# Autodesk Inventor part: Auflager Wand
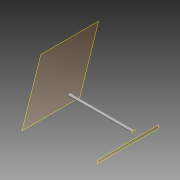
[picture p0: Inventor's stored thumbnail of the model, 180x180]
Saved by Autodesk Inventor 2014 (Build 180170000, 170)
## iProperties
Created: 2013-09
Part Number: Auflager Wand
Material: Stahl
Document SubType Name: Modeling
Designer: Stefan Tammegger
Mass: 71875.7 g
Surface Area: 45818.1 cm^2
Volume: 9156.13 cm^3
Density: 7.85 g/cm^3
Appearance: Stahl
Author: Stefan Tammegger
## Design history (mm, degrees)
node "Blöcke"
  sketch "FR 160_80_4"
    geometry: L1 (-2916.646, 2613.194)-(-2844.646, 2613.194); L2 (-2840.646, 2609.194)-(-2840.646, 2457.194); L3 (-2844.646, 2453.194)-(-2916.646, 2453.194); L4 (-2920.646, 2457.194)-(-2920.646, 2609.194); L5 (-2844.646, 2609.194)-(-2916.646, 2609.194); L6 (-2916.646, 2609.194)-(-2916.646, 2457.194); L7 (-2916.646, 2457.194)-(-2844.646, 2457.194); L8 (-2844.646, 2457.194)-(-2844.646, 2609.194); A1 r 4 centre (-2916.646, 2609.194) between (-2916.646, 2613.194) and (-2920.646, 2609.194); A2 r 4 centre (-2844.646, 2609.194) between (-2840.646, 2609.194) and (-2844.646, 2613.194); A3 r 4 centre (-2916.646, 2457.194) between (-2920.646, 2457.194) and (-2916.646, 2453.194); A4 r 4 centre (-2844.646, 2457.194) between (-2844.646, 2453.194) and (-2840.646, 2457.194); 4 further points
    constraints: 16 end point, 8 point on circle, 8 tangent, 6 point on line, 4 centre point, 4 parallel, 3 equal radius, 2 perpendicular, 1 horizontal, 1 midpoint, 3 other
    dimensions: "d0" = 80 distance of point (-2840.646, 2453.194) point (-2920.646, 2453.194); "d1" = 160 distance of point (-2840.646, 2613.194) point (-2840.646, 2453.194); "d2" = 4 distance between parallel lines of L1 L5; "d3" = 4 radius of A1
workplane "Arbeitsebene1"
sketch "Skizze1"
  geometry: L1 (-2996, 2490)-(-2924, 2490) reference; L2 (0, 30)-(-3300, 30) reference; L3 (0, 3800)-(0, -80) reference; L4 (-2996, 2490)-(490.681, 2795.045); L5 (-2996, 2490)-(504, 2490); L6 (-3000, 2334)-(-3000, 2486) reference; L7 (-2920, 2486)-(-2920, 2334) reference; A1 r 4 centre (-2996, 2486) between (-2996, 2490) and (-3000, 2486) reference; A2 r 4 centre (-2924, 2486) between (-2920, 2486) and (-2924, 2490) reference; 1 further point
  constraints: 4 end point, 1 equal length, 1 horizontal
  dimensions: "d4" = 20 dimension on L3; "d5" = 3500 distance of L1.start L4.end; "d6" = 5 deg angle of L5 L4; "d7" = 0 dimension on L4
  node "Referenz1"
  node "Referenz3"
  node "Referenz4"
  node "FR 160_80_4:1" dims "d4" = 20, "d5" = 3500, "d6" = 5 deg, "d7" = 0
  node "Referenz7"
  node "Referenz8"
  node "Referenz9"
  node "Referenz10"
workplane "Arbeitsebene2"
extrude "Extrusion1" new body sketch "Skizze1" stored distance "d8" = 10; taper "d9" = 0 deg
workplane "Arbeitsebene3"
feature "Trennen1"
workplane "Arbeitsebene4"
feature "Trennen2"
sketch "Skizze2"
  geometry: L1 (0, 0)-(-4526.608, 0) reference; L2 (-4462.605, 111)-(-4442.605, 111); L3 (-4462.605, 104)-(-4442.605, 104); L4 (-4442.605, 118)-(-4462.605, 118); L5 (-4462.605, 41)-(-4442.605, 41); L6 (-4462.605, 34)-(-4442.605, 34); L7 (-4442.605, 48)-(-4462.605, 48); C1 r 5.053 at (-4452.605, 111) reference; C2 r 5.053 at (-4452.605, 41) reference; A1 r 7 centre (-4462.605, 111) between (-4462.605, 118) and (-4462.605, 104); A2 r 7 centre (-4442.605, 111) between (-4442.605, 104) and (-4442.605, 118); A3 r 7 centre (-4462.605, 41) between (-4462.605, 48) and (-4462.605, 34); A4 r 7 centre (-4442.605, 41) between (-4442.605, 34) and (-4442.605, 48); 1 further point
  constraints: 16 end point, 8 point on circle, 8 tangent, 4 centre point, 4 parallel, 2 midpoint
  dimensions: "d10" = 10 distance of C1.centre L2.end; "d11" = 10 distance of C2.centre L5.end; "d14" = 14 distance between parallel lines of L3 L4; "d15" = 14 distance between parallel lines of L6 L7
extrude "Extrusion2" cut sketch "Skizze2" distance "d12" = 10; taper "d13" = 0 deg
sketch "Skizze4"
  geometry: L1 (-80, 0)-(-80, 152) reference; L2 (-4, -4)-(-76, -4) reference; L3 (-80, 246)-(0, 246); L4 (0, 246)-(0, -4); L5 (0, -4)-(-80, -4); L6 (-80, -4)-(-80, 246); 1 further point
  constraints: 8 end point, 2 collinear, 2 parallel, 1 horizontal, 1 perpendicular
  dimensions: "d23" = 80 distance of L4.end L5.end; "d24" = 250 distance of L3.end L4.end
extrude "Extrusion3" new body sketch "Skizze4" distance "d25" = 8; taper "d26" = 0 deg
sketch "Skizze5"
  geometry: L1 (0, 246)-(-80, 246) reference; L2 (-80, 246)-(-80, -4) reference; 2 further points
  dimensions: "d27" = 40 distance from line of L2 point (-40, 211); "d28" = 35 distance from line of L1 point (-40, 211)
hole "Bohrung2" sketch "Skizze5" at (-40, 211) diameter "d29" = 14; stored, may be unused: countersink angle "d33" = 90 deg, drill point angle "d35" = 118 deg; dims "d30" = 6, "d31" = 4, "d32" = 2, "d34" = 8
sketch "Skizze6"
  geometry: L1 (4545.557, 4)-(-0.997, 4) reference; L2 (4545.557, -76)-(18.949, -76) reference; L3 (4477.557, -6)-(4485.557, -6); L4 (4485.557, -6)-(4485.557, -66); L5 (4485.557, -66)-(4477.557, -66); L6 (4477.557, -66)-(4477.557, -6); L7 (4485.557, -3309.111)-(4485.557, 8.217) reference; 1 further point
  constraints: 8 end point, 2 parallel, 1 collinear, 1 horizontal, 1 perpendicular
  dimensions: "d36" = 8 distance of L4.end L5.end; "d37" = 60 distance of L3.end L4.end; "d38" = 10 distance between parallel lines of L1 L3
extrude "Extrusion4" new body sketch "Skizze6" distance "d39" = 90; taper "d40" = 0 deg
sketch "Skizze7"
  geometry: C1 r 7 at (30, 55) reference; 1 further point
hole "Bohrung3" sketch "Skizze7" at (30, 55) diameter "d41" = 14; stored, may be unused: countersink angle "d45" = 90 deg, drill point angle "d47" = 118 deg; dims "d42" = 6, "d43" = 4, "d44" = 2, "d46" = 8
sketch "Skizze8"
  geometry: L1 (4545.557, 4)-(-0.997, 4) reference; L2 (4545.557, -76)-(18.949, -76) reference; L3 (3635.557, -3309.111)-(3635.557, 8.217) reference; L4 (3695.557, 8.217)-(3695.557, -3309.111) reference; L5 (3627.557, -6)-(3635.557, -6); L6 (3635.557, -6)-(3635.557, -66); L7 (3635.557, -66)-(3627.557, -66); L8 (3627.557, -66)-(3627.557, -6); L9 (3695.557, -6)-(3703.557, -6); L10 (3703.557, -6)-(3703.557, -66); L11 (3703.557, -66)-(3695.557, -66); L12 (3695.557, -66)-(3695.557, -6); 1 further point
  constraints: 16 end point, 4 parallel, 3 collinear, 2 horizontal, 2 perpendicular
  dimensions: "d48" = 8 distance of L6.end L7.end; "d49" = 60 distance of L5.end L6.end; "d50" = 10 distance between parallel lines of L1 L5; "d51" = 8 distance of L10.end L11.end; "d52" = 60 distance of L9.end L10.end
extrude "Extrusion5" new body sketch "Skizze8" distance "d53" = 90; taper "d54" = 0 deg
pattern_linear "Rechteckige Anordnung1" dims "d64" = 850
sketch "Skizze10"
  geometry: L1 (80.464, 8.454)-(901.759, -3309.224) reference; L2 (839.975, -3309.334)-(22.223, -5.964) reference; L3 (84.518, -7.922)-(92.284, -6); L4 (92.284, -6)-(106.702, -64.242); L5 (106.702, -64.242)-(98.936, -66.164); L6 (98.936, -66.164)-(84.518, -7.922); L7 (4545.557, 4)-(-0.997, 4) reference; L8 (14.466, -7.922)-(22.231, -6); L9 (22.231, -6)-(36.649, -64.242); L10 (36.649, -64.242)-(28.884, -66.164); L11 (28.884, -66.164)-(14.466, -7.922); 1 further point
  constraints: 16 end point, 4 parallel, 2 collinear, 2 perpendicular
  dimensions: "d65" = 8 distance of L4.end L5.end; "d66" = 60 distance of L3.end L4.end; "d67" = 10 distance from line of L3.end L7; "d68" = 8 distance of L9.end L10.end; "d69" = 60 distance of L8.end L9.end; "d70" = 10 distance from line of L7 L8.end
extrude "Extrusion6" new body sketch "Skizze10" distance "d71" = 90; taper "d72" = 0 deg
sketch "Skizze11"
  geometry: L1 (-60, 90)-(0, 90) reference; L2 (-60, 0)-(-60, 90) reference; 2 further points
  dimensions: "d73" = 35 distance from line of point (-20, 55) L1; "d74" = 40 distance from line of L2 point (-20, 55)
hole "Bohrung5" sketch "Skizze11" at (-20, 55) diameter "d75" = 10.106; stored, may be unused: countersink angle "d79" = 90 deg, drill point angle "d81" = 118 deg; dims "d76" = 8, "d77" = 4, "d78" = 2, "d80" = 8
sketch "Skizze12"
  geometry: C1 r 5.053 at (-23.167, 55) reference; 1 further point
hole "Bohrung6" sketch "Skizze12" at (-23.167, 55) diameter "d82" = 14; stored, may be unused: countersink angle "d86" = 90 deg, drill point angle "d88" = 118 deg; dims "d83" = 8, "d84" = 4, "d85" = 2, "d87" = 12
sketch "Skizze13"
  geometry: C1 r 7 at (30, 55) reference; 1 further point
hole "Bohrung7" sketch "Skizze13" at (30, 55) diameter "d89" = 14; stored, may be unused: countersink angle "d93" = 90 deg, drill point angle "d95" = 118 deg; dims "d90" = 8, "d91" = 4, "d92" = 2, "d94" = 12
sketch "Skizze14"
  geometry: C1 r 7 at (4325.557, 32) reference; C2 r 7 at (4205.557, 32) reference; 1 further point
hole "Bohrung8" sketch "Skizze14" at (4325.557, 32), (4205.557, 32) diameter "d96" = 10.106; stored, may be unused: countersink angle "d100" = 90 deg, drill point angle "d102" = 118 deg; dims "d97" = 8, "d98" = 4, "d99" = 2, "d101" = 12
sketch "Skizze15"
  geometry: C1 r 7 at (1725.557, 32) reference; C2 r 7 at (1605.557, 32) reference; 1 further point
hole "Bohrung9" sketch "Skizze15" at (1605.557, 32), (1725.557, 32) diameter "d103" = 10.106; stored, may be unused: countersink angle "d107" = 90 deg, drill point angle "d109" = 118 deg; dims "d104" = 8, "d105" = 4, "d106" = 2, "d108" = 12
sketch "Skizze16"
  geometry: C1 r 7 at (4453.557, 11) reference; C2 r 7 at (4453.557, 61) reference; 1 further point
hole "Bohrung10" sketch "Skizze16" at (4453.557, 11), (4453.557, 61) diameter "d110" = 10.106; stored, may be unused: countersink angle "d114" = 90 deg, drill point angle "d116" = 118 deg; dims "d111" = 6, "d112" = 4, "d113" = 2, "d115" = 8
node "Volumenkörper1"
node "Referenz11"
node "Referenz12"
node "Volumenkörper2"
node "Volumenkörper3"
node "Referenz18"
node "Referenz19"
node "Referenz20"
node "Volumenkörper4"
node "Referenz22"
node "Referenz23"
node "Volumenkörper5"
node "Referenz24"
node "Referenz25"
node "Referenz26"
node "Referenz27"
node "Referenz28"
node "Referenz29"
node "Referenz30"
node "Referenz31"
